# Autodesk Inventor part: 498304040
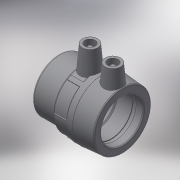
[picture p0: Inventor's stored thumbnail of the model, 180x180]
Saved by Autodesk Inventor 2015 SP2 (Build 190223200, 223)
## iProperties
Created: 2017-06
Part Number: 498304040
Material: Generic
Description: PLASSON WELDING CAP FOR TAPPING SADDLE TYPE-C
Document SubType Name: Modeling
Designer: KIM
Density: 1 g/cm^3
Appearance: Default
Author: KIM
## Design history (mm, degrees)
derived "498304_2.ipt"
feature "Solid1::498304_2.ipt"
tag "TaggingFeature1"
body "Solid1"
other parameters: "d7" = 1.53, "d8" = 19.25, "d10" = 1.02, "d11" = 11, "d12" = 168 deg, "d13" = 3.66667, "d14" = 40.6, "d15" = 49, "d16" = 15, "d17" = 31.5, "d18" = 1, "d20" = 5 deg, "d21" = 44.1, "d22" = 15, "d26" = 5 deg, "d27" = 4, "d29" = 14, "d30" = 0, "d31" = 4, "d33" = 14, "d34" = 0, "d46" = 3, "d47" = 0, "d48" = 3, "d49" = 0, "d50" = 63, "d51" = 51, "d52" = 56.1, "d53" = 58.14, "d54" = 55, "d55" = 135 deg, "d56" = 26, "d57" = 38.57, "d58" = 36.54, "d59" = 61.74, "d60" = 33.15, "d61" = 9.45, "d62" = 2.03, "d63" = 4.06, "d64" = 2.03, "d66" = 0, "d67" = 60 deg, "d69" = 360 deg, "d71" = 2.55, "d74" = 3.57, "d_" = 40.6, "L_" = 55, "L_1" = 26, "D_" = 51, "A_" = 49, "H_" = 63
